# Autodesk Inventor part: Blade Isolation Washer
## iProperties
Shininess: 64.0
Length Units: 11272
Angle Units: 11279
Time Units: 11290
Mass Units: 11286
Length Display Precision: 3
Angle Display Precision: 2
Compacted: True
Part Number: Blade Isolation Washer
Document SubType Name: Modeling
Created: 2003-08
Designer: jpittman
Manufacturer: Standard
Standards Organization: Custom
Density: 0.0
Volumn: 0.0
Area: 0.0
PropertySet Name: Model Information
Control State: 0
Master: False
Checked Out: False
Author: jpittman
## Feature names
1. Extrusion1
2. Extrusion2
